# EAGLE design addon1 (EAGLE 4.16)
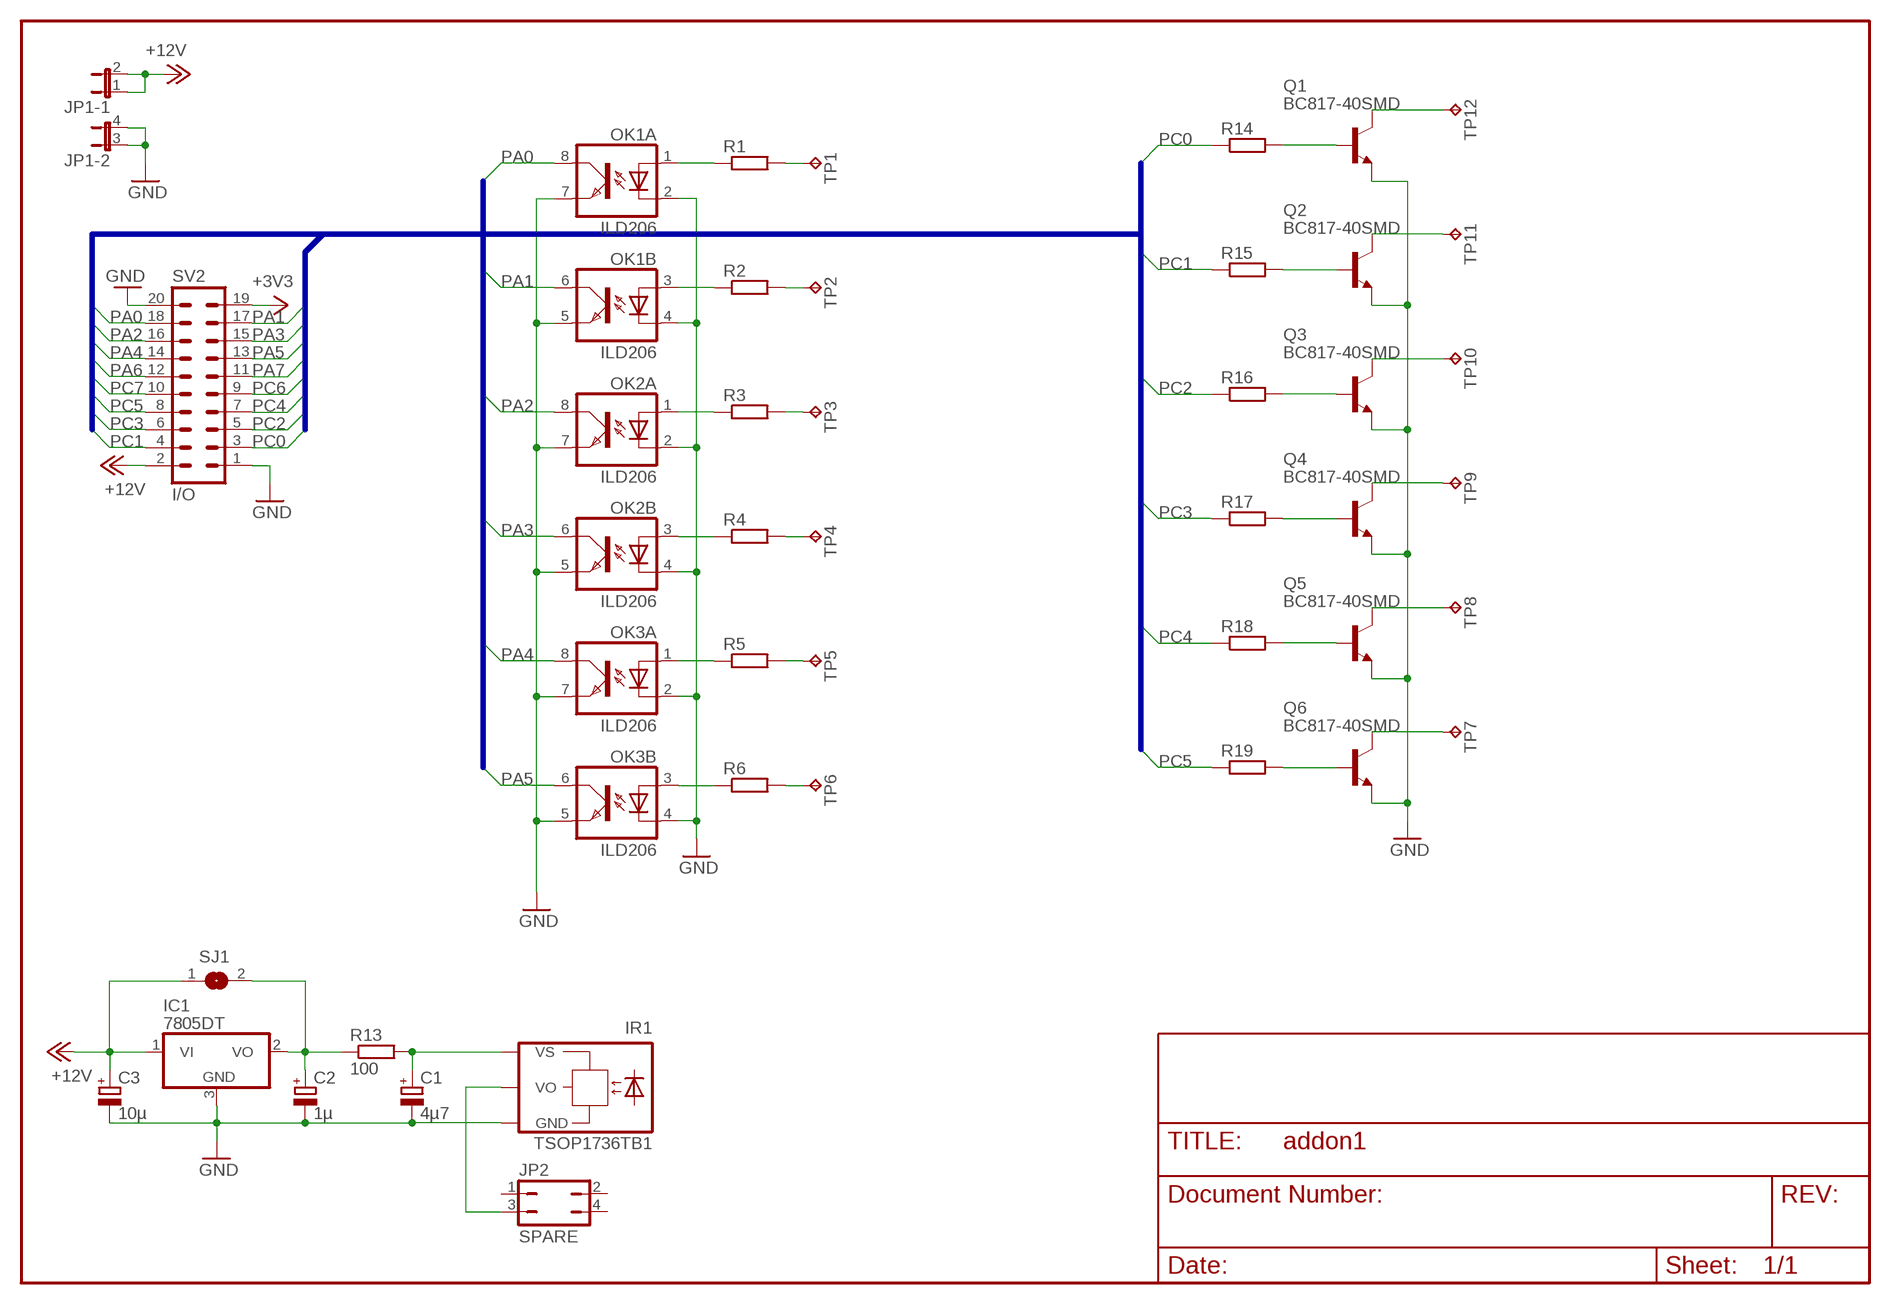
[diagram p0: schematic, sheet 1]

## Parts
C1  4µ7  CPOL-EUSMCA  [SMC_A]
C2  1µ  CPOL-EUSMCA  [SMC_A]
C3  10µ  CPOL-EUSMCD  [SMC_D]
IC1  7805DT  [TO252]
IR1  TSOP1736TB1  [TSOP17_TB1]
JP1  JP2QE  [JP2Q]
JP2  SPARE  JP2Q  [JP2Q]
OK1  ILD206  [SOIC08]
OK2  ILD206  [SOIC08]
OK3  ILD206  [SOIC08]
Q1  BC817-40SMD  [SOT23-BEC]
Q2  BC817-40SMD  [SOT23-BEC]
Q3  BC817-40SMD  [SOT23-BEC]
Q4  BC817-40SMD  [SOT23-BEC]
Q5  BC817-40SMD  [SOT23-BEC]
Q6  BC817-40SMD  [SOT23-BEC]
R1  R-EU_R0805  [R0805]
R2  R-EU_R0805  [R0805]
R3  R-EU_R0805  [R0805]
R4  R-EU_R0805  [R0805]
R5  R-EU_R0805  [R0805]
R6  R-EU_R0805  [R0805]
R13  100  R-EU_R0805  [R0805]
R14  R-EU_R0805  [R0805]
R15  R-EU_R0805  [R0805]
R16  R-EU_R0805  [R0805]
R17  R-EU_R0805  [R0805]
R18  R-EU_R0805  [R0805]
R19  R-EU_R0805  [R0805]
SJ1  SJ  [SJ]
SV2  I/O  MA10-2  [MA10-2]
TP1  TPPAD1-13Y  [P1-13Y]
TP2  TPPAD1-13Y  [P1-13Y]
TP3  TPPAD1-13Y  [P1-13Y]
TP4  TPPAD1-13Y  [P1-13Y]
TP5  TPPAD1-13Y  [P1-13Y]
TP6  TPPAD1-13Y  [P1-13Y]
TP7  TPPAD1-13Y  [P1-13Y]
TP8  TPPAD1-13Y  [P1-13Y]
TP9  TPPAD1-13Y  [P1-13Y]
TP10  TPPAD1-13Y  [P1-13Y]
TP11  TPPAD1-13Y  [P1-13Y]
TP12  TPPAD1-13Y  [P1-13Y]

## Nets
+3V3: SV2.19
+12V: C3.+ IC1.1(VI) JP1.1 JP1.2 SJ1.1 SV2.2
GND: C1.- C2.- C3.- IC1.3(GND) IR1.GND JP1.3 JP1.4 OK1.2(A:C) OK1.4(B:C) OK1.5(B:EMIT) OK1.7(A:EMIT) OK2.2(A:C) OK2.4(B:C) OK2.5(B:EMIT) OK2.7(A:EMIT) OK3.2(A:C) OK3.4(B:C) OK3.5(B:EMIT) OK3.7(A:EMIT) Q1.E Q2.E Q3.E Q4.E Q5.E Q6.E SV2.1 SV2.20
N$1: OK1.1(A:A) R1.1
N$2: R1.2 TP1.1(TP)
N$3: OK1.3(B:A) R2.1
N$4: R2.2 TP2.1(TP)
N$5: R3.2 TP3.1(TP)
N$6: OK2.1(A:A) R3.1
N$7: OK2.3(B:A) R4.1
N$8: R4.2 TP4.1(TP)
N$9: R5.2 TP5.1(TP)
N$10: OK3.1(A:A) R5.1
N$11: OK3.3(B:A) R6.1
N$12: R6.2 TP6.1(TP)
N$14: Q1.C TP12.1(TP)
N$15: Q2.C TP11.1(TP)
N$16: Q3.C TP10.1(TP)
N$17: Q4.C TP9.1(TP)
N$18: Q5.C TP8.1(TP)
N$19: Q6.C TP7.1(TP)
N$20: C2.+ IC1.2(VO) R13.1 SJ1.2
N$21: C1.+ IR1.VS R13.2
N$22: IR1.VO JP2.3
N$23: Q6.B R19.2
N$24: Q5.B R18.2
N$25: Q4.B R17.2
N$26: Q3.B R16.2
N$27: Q2.B R15.2
N$28: Q1.B R14.2
PA0: OK1.8(A:COL) SV2.18
PA1: OK1.6(B:COL) SV2.17
PA2: OK2.8(A:COL) SV2.16
PA3: OK2.6(B:COL) SV2.15
PA4: OK3.8(A:COL) SV2.14
PA5: OK3.6(B:COL) SV2.13
PA6: SV2.12
PA7: SV2.11
PC0: R14.1 SV2.3
PC1: R15.1 SV2.4
PC2: R16.1 SV2.5
PC3: R17.1 SV2.6
PC4: R18.1 SV2.7
PC5: R19.1 SV2.8
PC6: SV2.9
PC7: SV2.10
Unconnected: JP2.1 JP2.2 JP2.4

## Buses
PA[0..7],PC[0..7]

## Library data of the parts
C1-C3 = rcl:CPOL-EU: POLARIZED CAPACITOR, European symbol
IC1 = linear:78*: Positive VOLTAGE REGULATOR Source: http://cache.national.com/ds/LM/LM78L05.pdf http://www.fairchildsemi.com/ds/LM/LM7805.pdf
IR1 = telefunken:TSOP17*TB1: TSOP17..TB1 IR Receiver Modules for Remote Control Systems Source: http://www.vishay.com/docs/82042/82042.pdf
JP1 = jumper:JP2QE: JUMPER
JP2 = jumper:JP2Q: JUMPER
OK1-OK3 = optocoupler:ILD2*: Siemens ILD205/206/207/211/213/217 DUAL PHOTOTRANSISTOR SMALL OUTLINE SURFACE MOUNT OPTOCOUPLER Source: 153385-da-01-en-Optocoupler_ILD205-T.pdf
Q1-Q6 = transistor-npn:BC817*: NPN Transistor
R1-R6 R13-R19 = rcl:R-EU_: RESISTOR, European symbol
SJ1 = jumper:SJ: SMD solder JUMPER
SV2 = con-lstb:MA10-2: PIN HEADER
TP1-TP12 = testpad:TP

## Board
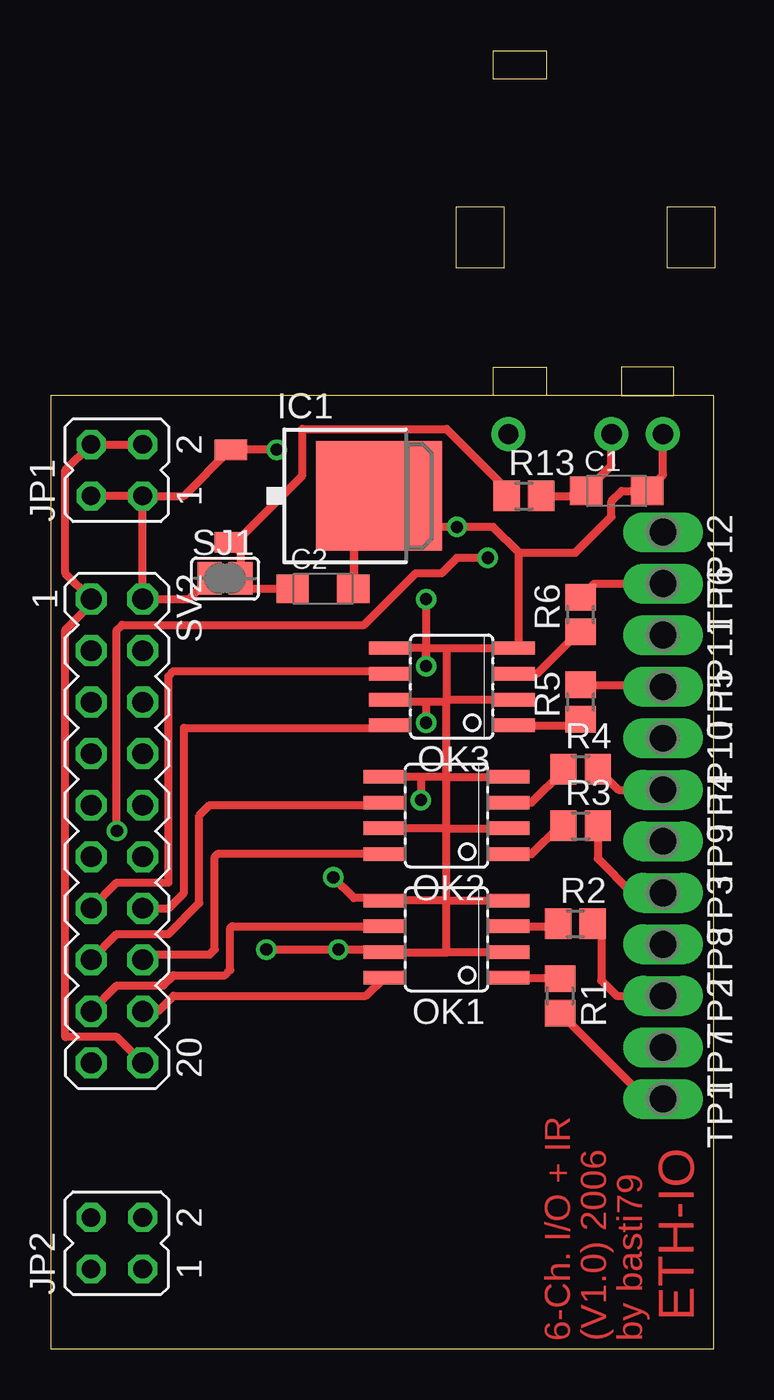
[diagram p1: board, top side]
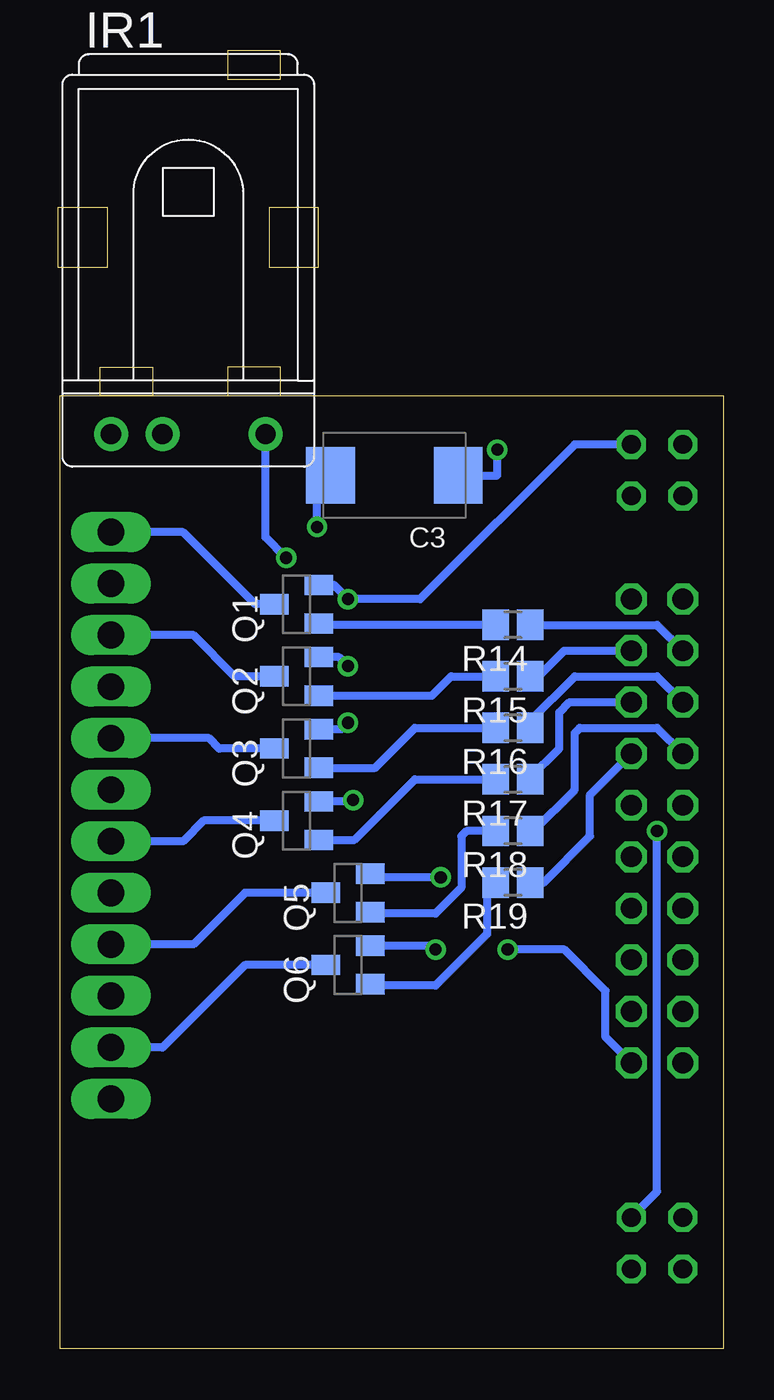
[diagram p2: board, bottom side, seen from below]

Size 32.78 x 63.98 mm. Coordinates in mm from the lower left corner, seen from the top.
Outline: 0,0 32.69,0 32.69,46.98 0,46.98 0,0
Copper layers (1*16): Top 0.035mm / dielectric 1.5mm / Bottom 0.035mm
Design rules "default": minimum track width 10mil, minimum drill 20mil, track to track 8mil, track to pad 8mil, pad to pad 8mil, via to via 8mil, smd to smd 8mil, copper to edge 20mil, drill to drill 8mil, minimum pad ring 10mil, minimum via ring 8mil, stop-mask expansion 4mil, vias tented up to drill 0mil, thermal gap 10mil
tKeepout: area 6.6,-0.1 to 23.3,16.9
bKeepout: area 6.6,-0.1 to 23.3,16.9; area 0,39.7 to 6.8,47.1; area 22.6,16.1 to 31.2,22.2

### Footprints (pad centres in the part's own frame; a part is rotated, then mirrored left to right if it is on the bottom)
SMC_A = smd 1.6 x 1.4: + -1.5,0; - 1.5,0
SMC_D = smd 2.4 x 2.8: + -3.15,0; - 3.15,0
TO252 = smd 1 x 1.6: 1 -2.28,-4.8; 2 2.28,-4.8 | smd 5.4 x 6.2: 3 0,2.5
TSOP17_TB1 = drill 1 pad 1.676 round: GND 0,-3.81; VO 0,3.81; VS 0,-1.27
JP2Q = drill 0.914 octagon: 1 -1.27,-1.27; 2 -1.27,1.27; 3 1.27,-1.27; 4 1.27,1.27
SOIC08 = smd 0.66 x 2.032: 1 -1.905,-3.073; 2 -0.635,-3.073; 3 0.635,-3.073; 4 1.905,-3.073; 5 1.905,3.073; 6 0.635,3.073; 7 -0.635,3.073; 8 -1.905,3.073
SOT23-BEC = smd 1 x 1.4: B -0.95,-1.1; C 0,1.1; E 0.95,-1.1
R0805 = smd 1.3 x 1.5: 1 -0.85,0; 2 0.85,0
SJ = smd 1.168 x 1.6: 1 -0.762,0; 2 0.762,0
MA10-2 = drill 1.016 octagon: 1 -11.43,-1.27; 2 -11.43,1.27; 3 -8.89,-1.27; 4 -8.89,1.27; 5 -6.35,-1.27; 6 -6.35,1.27; 7 -3.81,-1.27; 8 -3.81,1.27; 9 -1.27,-1.27; 10 -1.27,1.27; 11 1.27,-1.27; 12 1.27,1.27; 13 3.81,-1.27; 14 3.81,1.27; 15 6.35,-1.27; 16 6.35,1.27; 17 8.89,-1.27; 18 8.89,1.27; 19 11.43,-1.27; 20 11.43,1.27
P1-13Y = drill 1.321 pad 1.905 long: 1 0,0

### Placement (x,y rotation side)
C1  27.9,42.29 0 top
C2  13.42,37.46 0 top
C3  16.22,43.05 180 bottom
IC1  13.68,42.03 270 top
IR1  26.38,45.08 270 bottom
JP1  3.26,43.3 90 top
JP2  3.26,5.2 90 top
OK1  19.52,20.19 90 top
OK2  19.52,26.28 90 top
OK3  19.77,32.63 90 top
Q1  21.04,36.7 90 bottom
Q2  21.04,33.14 90 bottom
Q3  21.04,29.59 90 bottom
Q4  21.04,26.03 90 bottom
Q5  18.5,22.47 90 bottom
Q6  18.5,18.92 90 bottom
R1  25.11,17.39 270 top
R2  25.87,20.95 0 top
R3  26.12,25.78 0 top
R4  26.12,28.57 0 top
R5  26.12,31.87 90 top
R6  26.12,36.19 90 top
R13  23.33,42.03 0 top
R14  10.38,35.68 180 bottom
R15  10.38,33.14 180 bottom
R16  10.38,30.6 180 bottom
R17  10.38,28.06 180 bottom
R18  10.38,25.52 180 bottom
R19  10.38,22.98 180 bottom
SJ1  8.6,37.97 0 top
SV2  3.26,25.52 270 top
TP1  30.19,12.31 270 top
TP2  30.19,17.39 270 top
TP3  30.19,22.47 270 top
TP4  30.19,27.55 270 top
TP5  30.19,32.63 270 top
TP6  30.19,37.71 270 top
TP7  30.19,14.85 270 top
TP8  30.19,19.93 270 top
TP9  30.19,25.01 270 top
TP10  30.19,30.09 270 top
TP11  30.19,35.17 270 top
TP12  30.19,40.25 270 top

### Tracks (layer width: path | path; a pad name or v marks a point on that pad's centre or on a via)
+12V  (via drill 0.6)
  Top 0.406: SJ1.1 6.82,36.95 SV2.2 JP1.1 | JP1.1 JP1.2 | JP1.1 6.57,42.03 8.85,44.32 8.86,44.31 IC1.1 9.11,44.31 9.11,44.32 v11.14,44.32
  Bottom 0.406: C3.+ 11.14,43.05 v11.14,44.32
GND  (via drill 0.6)
  Top 0.406: OK3.7 16.57,31.87 18.5,31.87 | 16.47,19.53 16.47,19.43 | 16.47,19.53 OK1.7 16.45,19.66 16.47,19.68 v14.19,19.68 v10.63,19.68 | SV2.20 3.26,15.36 0.72,15.36 0.72,35.43 1.99,36.7 SV2.1 0.72,38.22 0.72,43.3 JP1.4 JP1.3 | 16.47,19.53 19.52,19.53 19.52,19.68 | OK1.2 19.52,19.55 19.52,19.68 | 19.52,22.09 OK1.5 16.47,22.12 16.47,22.22 14.95,22.22 v13.93,23.24 | 19.52,19.68 19.52,21.97 | 19.52,22.09 OK1.4 | 19.52,21.97 19.52,22.09 | 19.52,25.65 OK2.7 | 19.52,21.97 19.52,25.52 | 19.52,25.65 OK2.2 | 19.52,25.52 19.52,25.65 | 19.52,28.19 18.25,28.19 | 18.25,28.19 OK2.5 | 19.52,25.52 19.52,28.06 | 19.52,28.19 OK2.4 | 19.52,28.06 19.52,28.19 | 19.52,31.87 18.5,31.87 | OK3.2 19.52,32 19.52,31.87 | 19.52,28.06 19.52,31.87 | 18.5,34.54 OK3.5 | 18.5,34.54 19.52,34.54 | 19.52,34.54 OK3.4 23.08,34.77 23.08,39.24 | 19.52,34.54 19.52,31.87 | IR1.GND 30.19,43.07 C1.- 28.16,42.29 27.65,41.78 27.65,41.02 25.87,39.24 23.08,39.24 | 18.5,34.54 v18.5,33.65 v18.5,36.95 | 18.5,31.87 v18.5,30.86 | 18.25,28.19 v18.25,27.05 | IC1.3 18,42.54 | 23.08,39.24 21.81,40.51 v20.03,40.51 14.95,40.51 14.95,37.46 | 14.95,37.46 C2.- | 14.95,37.46 14.95,42.03 IC1.3 | IC1.3 16.22,42.03
  Bottom 0.406: Q2.E 18.95,34.09 v18.5,33.65 | Q3.E 18.82,30.54 v18.5,30.86 | Q4.E 18.32,26.98 v18.25,27.05 | Q5.E 17.22,23.24 v13.93,23.24 | Q1.E 19.2,37.65 v18.5,36.95 14.95,36.95 7.33,44.57 JP1.3 | Q6.E 14.37,19.87 v14.19,19.68 | SV2.20 5.8,15.36 5.8,17.65 7.84,19.68 v10.63,19.68 | C3.- 20.03,43.05 v20.03,40.51
N$1
  Top 0.406: 25.11,18.16 R1.1 25.11,18.28 OK1.1
N$2
  Top 0.406: R1.2 29.34,12.31 TP1.1
N$3
  Top 0.406: R2.1 24.85,20.95 arc-90 24.73,20.82 OK1.3
N$4
  Top 0.406: R2.2 27.14,20.53 27.14,18.16 27.9,17.39 TP2.1
N$5
  Top 0.406: R3.2 26.97,24.16 28.66,22.47 TP3.1
N$6
  Top 0.406: R3.1 25.11,25.78 23.71,24.38 OK2.1
N$7
  Top 0.406: OK2.3 23.71,26.92 25.27,28.48 R4.1
N$8
  Top 0.406: R4.2 27.99,27.55 TP4.1
N$9
  Top 0.406: R5.2 30.1,32.72 TP5.1
N$10
  Top 0.406: R5.1 26.12,31.11 25.74,30.73 OK3.1
N$11
  Top 0.406: OK3.3 23.96,33.27 26.04,35.34 R6.1
N$12
  Top 0.406: R6.2 26.8,37.71 TP6.1
N$14
  Bottom 0.406: Q1.C 23.08,36.7 26.63,40.25 TP12.1
N$15
  Bottom 0.406: Q2.C 24.09,33.14 26.12,35.17 TP11.1
N$16
  Bottom 0.406: Q3.C 24.85,29.59 25.36,30.09 TP10.1
N$17
  Bottom 0.406: Q4.C 25.62,26.03 26.63,25.01 TP9.1
N$18
  Bottom 0.406: Q5.C 23.58,22.47 26.12,19.93 TP8.1
N$19
  Bottom 0.406: 30.44,14.85 TP7.1 27.65,14.85 23.58,18.92 Q6.C
N$20
  Top 0.406: R13.1 22.48,42.37 19.52,45.33 12.41,45.33 12.41,43.05 9.11,39.75 9.1,39.75 IC1.2 8.86,39.75 8.85,39.75 9.36,39.24 SJ1.2 9.36,37.46 C2.+
N$21
  Top 0.406: IR1.VS 27.65,43.53 C1.+ 26.12,42.29 25.87,42.03 R13.2
N$22  (via drill 0.6)
  Top 0.406: v3.26,25.52 3.26,35.43 3.52,35.68 15.46,35.68 18,38.22 19.27,38.22 20.03,38.98 v21.55,38.98
  Bottom 0.406: JP2.3 3.26,7.74 v3.26,25.52 | v21.55,38.98 22.57,40 IR1.VO
N$23
  Bottom 0.406: R19.2 11.65,22.56 11.65,20.44 14.19,17.9 17.34,17.9 Q6.B
N$24
  Bottom 0.406: R18.2 12.66,25.52 12.92,25.27 12.92,22.73 14.19,21.46 17.34,21.46 Q5.B
N$25
  Bottom 0.406: Q4.B 18.18,25.08 15.2,28.06 R17.2
N$26
  Bottom 0.406: Q3.B 17.17,28.64 15.2,30.6 R16.2 11.14,30.6
N$27
  Bottom 0.406: Q2.B 14.37,32.19 13.42,33.14 R15.2
N$28
  Bottom 0.406: Q1.B 19.84,35.75 19.77,35.68 R14.2
PA0
  Top 0.406: OK1.8 15.56,17.39 6.06,17.39 5.3,16.63 SV2.18
PA1
  Top 0.406: SV2.17 3.26,17.9 5.55,17.9 6.06,18.41 8.6,18.41 8.85,18.66 8.85,20.7 arc-90 8.98,20.82 OK1.6
PA2
  Top 0.406: SV2.16 4.79,19.43 7.84,19.43 8.09,19.68 8.09,24.25 8.22,24.38 OK2.8
PA3
  Top 0.406: SV2.15 3.26,20.44 5.8,20.44 7.33,21.97 7.33,26.28 7.84,26.79 16.32,26.79 OK2.6
PA4
  Top 0.406: SV2.14 5.8,21.71 6.57,22.47 6.57,30.6 16.73,30.6 16.73,30.7 OK3.8
PA5
  Top 0.406: SV2.13 3.26,22.98 5.8,22.98 5.8,33.14 6.06,33.4 16.73,33.4 16.73,33.29 OK3.6
PC0
  Bottom 0.406: R14.1 3.26,35.68 SV2.3
PC1
  Bottom 0.406: R15.1 9.11,33.14 7.84,34.41 SV2.4
PC2
  Bottom 0.406: R16.1 9.53,30.94 7.33,33.14 3.26,33.14 SV2.5
PC3
  Bottom 0.406: R17.1 9.53,28.15 8.09,29.59 8.09,31.36 7.58,31.87 SV2.6
PC4
  Bottom 0.406: R18.1 9.36,25.52 7.33,27.55 7.33,30.35 7.07,30.6 3.26,30.6 SV2.7
PC5
  Bottom 0.406: R19.1 8.85,22.98 6.57,25.27 6.57,27.3 SV2.8

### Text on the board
Top: ETH-IO | 6-Ch. I/O + IR | (V1.0) 2006 | by basti79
